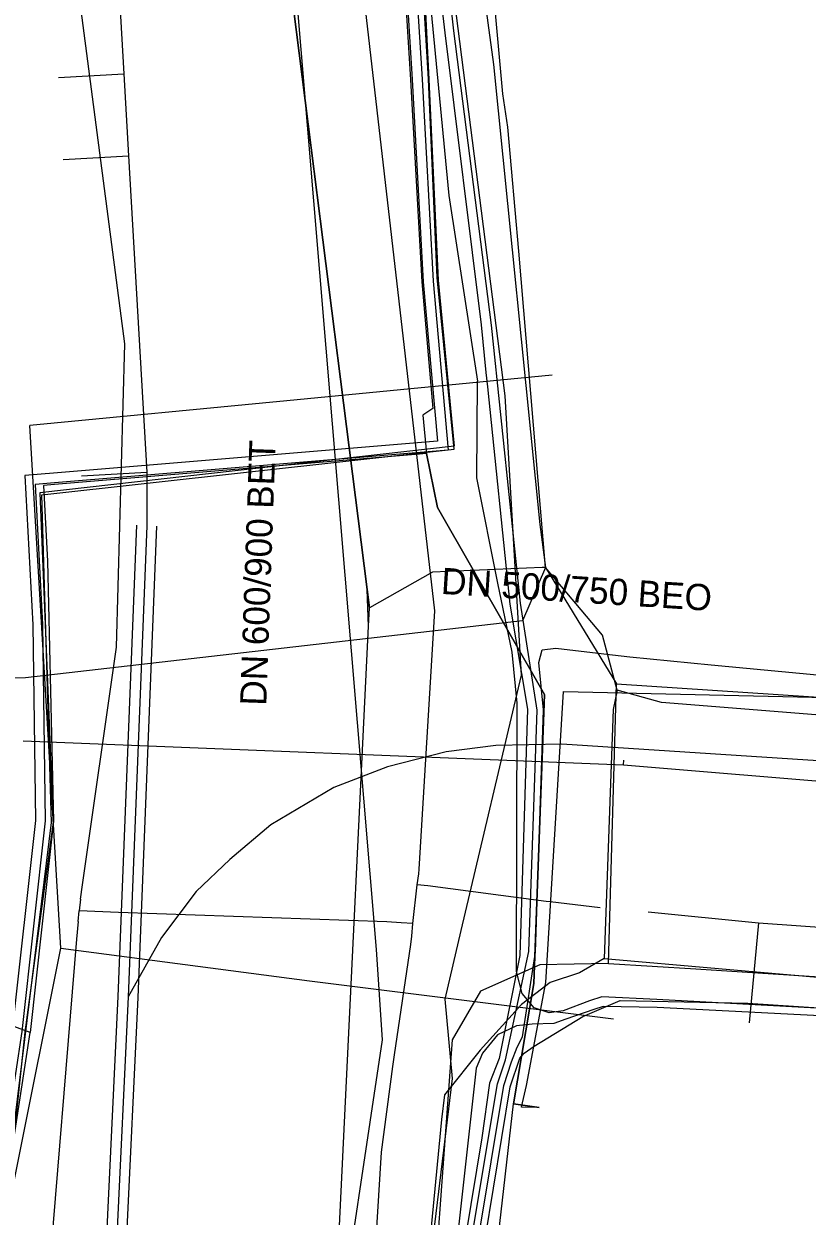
# Model space of a CAD drawing. Extents: x -600309 to -598967, y -1161267 to -1160292.
# Drawn here: x -599086.65 to -599062.77, y -1160939.36 to -1160903.03 of the extents above; entities that cross this region are included whole.
import ezdxf

# ---------------------------------------------------------------- set-up
doc = ezdxf.new("R2010")
doc.units = 0
for name, color, linetype in [('Vrstva 10', 7, 'Continuous'), ('Vrstva 12', 7, 'Continuous'), ('Vrstva 13', 7, 'Continuous'), ('Vrstva 16', 7, 'Continuous'), ('Vrstva 19', 7, 'Continuous'), ('Vrstva 42', 7, 'Continuous'), ('Vrstva 43', 7, 'Continuous'), ('Vrstva 44', 7, 'Continuous'), ('Vrstva 54', 7, 'Continuous'), ('Vrstva 55', 7, 'Continuous'), ('Vrstva 58', 7, 'Continuous'), ('Vrstva 9', 7, 'Continuous')]:
    doc.layers.add(name, color=color, linetype=linetype)

msp = doc.modelspace()

# ---------------------------------------------------------------- linework, layer by layer
at = {"layer": 'Vrstva 10'}
for p, q in [((-599083.771, -1160932.673), (-599083.205, -1160918.311)), ((-599082.605, -1160918.335), (-599083.172, -1160932.697)), ((-599085.318, -1160965.214), (-599083.771, -1160932.67)), ((-599083.172, -1160932.699), (-599084.718, -1160965.242))]:
    msp.add_line(p, q, dxfattribs=at)
for points in [[(-599076.11, -1160920.83), (-599076.18, -1160920.27), (-599081.77, -1160876.19), (-599081.84, -1160875.63)], [(-599078.52, -1160970.46), (-599078.49, -1160969.9), (-599076.14, -1160921.39), (-599076.11, -1160920.83)]]:
    msp.add_lwpolyline(points, dxfattribs=at)
at = {"layer": 'Vrstva 12'}
for points in [[(-599081.84, -1160875.63), (-599076.18, -1160920.27)], [(-599076.75, -1160961.37), (-599073.58, -1160935.17), (-599073.8, -1160932.75), (-599073.32, -1160930.66), (-599071.48, -1160922.88), (-599071.97, -1160914.37), (-599075.73, -1160885.06), (-599076.28, -1160881.3)], [(-599075.51, -1160886.01), (-599075.22, -1160888.16), (-599074.18, -1160890.67), (-599072.33, -1160904.27), (-599070.92, -1160918.29), (-599070.74, -1160919.6)], [(-599070.74, -1160919.6), (-599070.85, -1160919.6), (-599074.19, -1160919.74), (-599076.11, -1160920.83)], [(-599070.74, -1160919.6), (-599068.58, -1160923.14)], [(-599076.18, -1160920.27), (-599076.11, -1160920.83)], [(-599078.52, -1160970.46), (-599078.49, -1160969.9), (-599076.14, -1160921.39), (-599076.11, -1160920.83)], [(-599068.82, -1160931.67), (-599068.58, -1160923.14)], [(-599068.58, -1160923.14), (-599049.94, -1160924.37), (-599041.48, -1160924.88)], [(-599068.82, -1160931.67), (-599070.92, -1160931.71), (-599072.73, -1160932.51), (-599073.59, -1160933.99), (-599074.3, -1160943.74)], [(-599068.82, -1160931.67), (-599066.16, -1160931.83)], [(-599066.16, -1160931.83), (-599060.5, -1160932.19), (-599051.79, -1160932.95), (-599048.6, -1160933.22), (-599040.36, -1160933.93)]]:
    msp.add_lwpolyline(points, dxfattribs=at)
at = {"layer": 'Vrstva 13'}
msp.add_line((-599068.368, -1160925.609), (-599068.355, -1160925.474), dxfattribs=at)
for points in [[(-599086.629, -1161017.283), (-599085.561, -1161009.137), (-599084.815, -1161003.441), (-599084.71, -1161002.64), (-599080.51, -1160970.65), (-599080.1, -1160967.363), (-599079.637, -1160963.654), (-599079.404, -1160961.786), (-599078, -1160950.54), (-599077.19, -1160943.82), (-599075.71, -1160933.99), (-599075.9, -1160931.24), (-599079.535, -1160887.787)], [(-599086.676, -1160924.879), (-599068.368, -1160925.609), (-598967.108, -1160934.03)]]:
    msp.add_lwpolyline(points, dxfattribs=at)
at = {"layer": 'Vrstva 16'}
for points in [[(-599067.61, -1160930.089), (-599064.25, -1160930.43), (-599044.31, -1160931.84), (-599028.16, -1160932.91), (-599026.61, -1160933.02), (-599013.61, -1160934), (-598996.41, -1160935.24), (-598988.49, -1160935.92), (-598977.06, -1160936.9), (-598975.76, -1160937.03), (-598967.108, -1160937.639)], [(-599064.25, -1160930.43), (-599064.53, -1160933.47)]]:
    msp.add_lwpolyline(points, dxfattribs=at)
at = {"layer": 'Vrstva 19'}
for points in [[(-599084.92, -1160929.7), (-599084.859, -1160929.27), (-599083.83, -1160922.03), (-599083.57, -1160912.78), (-599095.07, -1160825.37), (-599102.5, -1160768.3), (-599104.6, -1160752.25), (-599109.62, -1160709.21), (-599119.67, -1160628.93), (-599126.32, -1160575.37), (-599128.11, -1160560.16), (-599133.16, -1160522.31), (-599135.34, -1160510.45), (-599143.35, -1160452.12)], [(-599069.08, -1160929.97), (-599070.6, -1160929.79), (-599070.722, -1160929.774), (-599074.33, -1160929.3), (-599074.66, -1160929.27), (-599074.61, -1160928.93), (-599074.6, -1160928.79), (-599074.12, -1160920.92), (-599077.86, -1160888.45)], [(-599074.85, -1160931.09), (-599074.82, -1160930.83), (-599074.79, -1160930.45), (-599074.66, -1160929.27)], [(-599084.92, -1160929.7), (-599084.96, -1160930.06)], [(-599085, -1160930.39), (-599084.96, -1160930.06)], [(-599075.15, -1160930.43), (-599075.58, -1160930.4), (-599083.77, -1160930.11), (-599084.96, -1160930.06)], [(-599085, -1160930.39), (-599085.044, -1160930.926), (-599085.95, -1160941.91), (-599090.16, -1160981.76)], [(-599074.79, -1160930.45), (-599075.15, -1160930.43)], [(-599085.33, -1161002.59), (-599085.26, -1161001.65), (-599085.24, -1161001.33), (-599085.15, -1161000.04), (-599083.59, -1160988.06), (-599081.79, -1160972.81), (-599080.96, -1160967.67), (-599080.84, -1160966.69), (-599080.29, -1160962.23), (-599080.14, -1160961.28), (-599079.55, -1160955.17), (-599078.82, -1160954.67), (-599077.47, -1160953.6), (-599077.19, -1160953.33), (-599077.12, -1160952.91), (-599076.35, -1160947.15), (-599075.75, -1160937.41), (-599075.4, -1160934.8), (-599075.35, -1160934.45), (-599074.85, -1160931.09)]]:
    msp.add_lwpolyline(points, dxfattribs=at)
at = {"layer": 'Vrstva 42'}
for points in [[(-599074.82, -1160894.78), (-599073.81, -1160903.3), (-599072.71, -1160912.2), (-599072.56, -1160913.652), (-599072.514, -1160914.094), (-599071.83, -1160920.71), (-599071.29, -1160923.91), (-599071.53, -1160931.42), (-599072.16, -1160934.56), (-599072.45, -1160935.31), (-599072.684, -1160936.976), (-599073.187, -1160939.993), (-599073.432, -1160945.786), (-599073.555, -1160946.606), (-599073.561, -1160946.827), (-599073.433, -1160947.128), (-599072.812, -1160947.002)], [(-599072.786, -1160946.793), (-599073.313, -1160946.9), (-599073.36, -1160946.789), (-599073.355, -1160946.624), (-599073.233, -1160945.805), (-599072.988, -1160940.014), (-599072.207, -1160935.333), (-599071.967, -1160934.598), (-599071.25, -1160931.3), (-599071, -1160923.95), (-599071.51, -1160920.68), (-599072.39, -1160912.21), (-599073.54, -1160903.24), (-599074.49, -1160894.73)], [(-599097.718, -1161019.921), (-599095.763, -1161007.197), (-599095.192, -1161003.648), (-599094.56, -1160998.354), (-599094.831, -1160996.489), (-599094.44, -1160992.187), (-599093.567, -1160984.908), (-599091.161, -1160967.703), (-599091.973, -1160964.785), (-599091.582, -1160962.168), (-599090.198, -1160959.942), (-599089.086, -1160950.617), (-599089.687, -1160948.061), (-599089.838, -1160946.015), (-599089.356, -1160943.609), (-599087.792, -1160941.233), (-599087.07, -1160937.623), (-599085.807, -1160927.366), (-599086.108, -1160917.38), (-599073.534, -1160915.996), (-599074.046, -1160910.762), (-599074.316, -1160904.716), (-599074.708, -1160898.099)], [(-599074.921, -1160898.144), (-599074.51, -1160904.711), (-599074.17, -1160910.869), (-599073.712, -1160916.021), (-599085.717, -1160917.019), (-599086.309, -1160917.072), (-599086.08, -1160921.335), (-599086, -1160927.317), (-599086.711, -1160933.739), (-599087.292, -1160937.576), (-599088.039, -1160941.249), (-599089.588, -1160943.548), (-599090.049, -1160946.009), (-599089.921, -1160948.018), (-599089.308, -1160950.68), (-599089.601, -1160953.945), (-599089.737, -1160955.126), (-599090.356, -1160959.945), (-599090.555, -1160960.234), (-599090.822, -1160961.928)], [(-599074.921, -1160898.144), (-599074.51, -1160904.711), (-599074.17, -1160910.869), (-599073.712, -1160916.021), (-599085.717, -1160917.019), (-599086.309, -1160917.072), (-599086.08, -1160921.335), (-599086, -1160927.317), (-599086.711, -1160933.739), (-599087.292, -1160937.576), (-599088.039, -1160941.249), (-599089.588, -1160943.548), (-599090.049, -1160946.009), (-599089.921, -1160948.018), (-599089.308, -1160950.68), (-599089.601, -1160953.945), (-599089.737, -1160955.126), (-599090.356, -1160959.945), (-599090.555, -1160960.234), (-599090.822, -1160961.928)], [(-599075.219, -1160898.176), (-599074.81, -1160904.729), (-599074.47, -1160910.891), (-599074.038, -1160915.747), (-599085.743, -1160916.721), (-599086.625, -1160916.798), (-599086.38, -1160921.345), (-599086.3, -1160927.303), (-599087.009, -1160933.701), (-599087.588, -1160937.524), (-599088.321, -1160941.131), (-599089.872, -1160943.432), (-599090.351, -1160945.991), (-599090.219, -1160948.062), (-599089.612, -1160950.7), (-599089.899, -1160953.915), (-599090.035, -1160955.09), (-599090.644, -1160959.835)], [(-599075.219, -1160898.176), (-599074.81, -1160904.729), (-599074.47, -1160910.891), (-599074.038, -1160915.747), (-599085.743, -1160916.721), (-599086.625, -1160916.798), (-599086.38, -1160921.345), (-599086.3, -1160927.303), (-599087.009, -1160933.701), (-599087.588, -1160937.524), (-599088.321, -1160941.131), (-599089.872, -1160943.432), (-599090.351, -1160945.991), (-599090.219, -1160948.062), (-599089.612, -1160950.7), (-599089.899, -1160953.915), (-599090.035, -1160955.09), (-599090.644, -1160959.835)], [(-599074.921, -1160898.144), (-599074.51, -1160904.711), (-599074.17, -1160910.869), (-599073.712, -1160916.021), (-599085.717, -1160917.019), (-599086.309, -1160917.072), (-599086.08, -1160921.335), (-599086, -1160927.317), (-599086.711, -1160933.739), (-599087.292, -1160937.576), (-599088.039, -1160941.249), (-599089.588, -1160943.548), (-599090.049, -1160946.009), (-599089.921, -1160948.018), (-599089.308, -1160950.68), (-599089.601, -1160953.945), (-599089.737, -1160955.126), (-599090.356, -1160959.945)], [(-599074.921, -1160898.144), (-599074.51, -1160904.711), (-599074.17, -1160910.869), (-599073.712, -1160916.021), (-599085.717, -1160917.019), (-599086.309, -1160917.072), (-599086.08, -1160921.335), (-599086, -1160927.317), (-599086.711, -1160933.739), (-599087.292, -1160937.576), (-599088.039, -1160941.249), (-599089.588, -1160943.548), (-599090.049, -1160946.009), (-599089.921, -1160948.018), (-599089.308, -1160950.68), (-599089.601, -1160953.945), (-599089.737, -1160955.126), (-599090.356, -1160959.945)], [(-599075.219, -1160898.176), (-599074.81, -1160904.729), (-599074.47, -1160910.891), (-599074.038, -1160915.747), (-599085.743, -1160916.721), (-599086.625, -1160916.798), (-599086.38, -1160921.345), (-599086.3, -1160927.303), (-599087.009, -1160933.701), (-599087.588, -1160937.524), (-599088.321, -1160941.131), (-599089.872, -1160943.432), (-599090.351, -1160945.991), (-599090.219, -1160948.062), (-599089.612, -1160950.7), (-599088.763, -1160946.288)], [(-599075.219, -1160898.176), (-599074.81, -1160904.729), (-599074.47, -1160910.891), (-599074.038, -1160915.747), (-599085.743, -1160916.721), (-599086.625, -1160916.798), (-599086.38, -1160921.345), (-599086.3, -1160927.303), (-599087.009, -1160933.701), (-599087.588, -1160937.524), (-599088.321, -1160941.131), (-599089.872, -1160943.432), (-599090.351, -1160945.991), (-599090.219, -1160948.062), (-599089.612, -1160950.7), (-599088.763, -1160946.288)], [(-599072.761, -1160946.584), (-599073.115, -1160946.658), (-599073.154, -1160946.632), (-599073.033, -1160945.825), (-599072.788, -1160940.034), (-599072.013, -1160935.381), (-599071.777, -1160934.66), (-599071.61, -1160934.22), (-599071.45, -1160933.9), (-599071.05, -1160931.322), (-599070.801, -1160923.939), (-599070.95, -1160922.49), (-599070.85, -1160922.11), (-599070.43, -1160922.06), (-599068.965, -1160922.225), (-599068.17, -1160922.32), (-599065.69, -1160922.56), (-599062.46, -1160922.87)], [(-599072.735, -1160946.374), (-599072.88, -1160946.403), (-599072.914, -1160946.381), (-599072.834, -1160945.844), (-599072.589, -1160940.055), (-599071.818, -1160935.429), (-599071.53, -1160934.546), (-599071.4, -1160934.4), (-599071.09, -1160934.18), (-599069.61, -1160933.28), (-599068.47, -1160932.79), (-599064.57, -1160932.87), (-599059.79, -1160933.19)]]:
    msp.add_lwpolyline(points, dxfattribs=at)
at = {"layer": 'Vrstva 43'}
for points in [[(-599070.74, -1160919.6), (-599071.45, -1160921.22), (-599086.6, -1160922.96), (-599089.07, -1160922.98)], [(-599068.56, -1160923.34), (-599069.01, -1160921.66), (-599070.74, -1160919.6)], [(-599059.45, -1160924.33), (-599067.21, -1160923.71), (-599068.56, -1160923.34)]]:
    msp.add_lwpolyline(points, dxfattribs=at)
at = {"layer": 'Vrstva 44'}
for points in [[(-599112.09, -1160608.13), (-599111.98, -1160609.99), (-599109.504, -1160629.736), (-599106.065, -1160655.324), (-599103.642, -1160674.134), (-599100.509, -1160697.439), (-599095.391, -1160735.084), (-599093.34, -1160750.202), (-599089.712, -1160777.364), (-599087.879, -1160792.317), (-599087.434, -1160795.875), (-599084.392, -1160820.684), (-599084.024, -1160822.578), (-599080.74, -1160848.464), (-599078.594, -1160865.22), (-599075.405, -1160890.518), (-599073.694, -1160908.257), (-599072.822, -1160913.918)], [(-599060.79, -1160933.12), (-599067.35, -1160932.76), (-599069.03, -1160932.68), (-599069.4, -1160932.8), (-599070.21, -1160933.11), (-599070.63, -1160933.17), (-599071.09, -1160933.02), (-599071.46, -1160932.58), (-599071.63, -1160931.91), (-599071.61, -1160923.73), (-599071.76, -1160922.18), (-599072.2, -1160920.07), (-599072.84, -1160916.86), (-599072.822, -1160913.918)], [(-599060.78, -1160933.34), (-599067.34, -1160933.01), (-599068.99, -1160932.98), (-599069.27, -1160933.07), (-599070.12, -1160933.36), (-599070.49, -1160933.49), (-599071.15, -1160933.51), (-599071.63, -1160933.57), (-599072.21, -1160933.84), (-599072.67, -1160934.4), (-599072.86, -1160934.86), (-599073.46, -1160940.25), (-599074.2, -1160945.93), (-599074.134, -1160949.259)]]:
    msp.add_lwpolyline(points, dxfattribs=at)
at = {"layer": 'Vrstva 54'}
for points in [[(-599070.54, -1160913.74), (-599078.63, -1160914.52)], [(-599078.63, -1160914.52), (-599086.47, -1160915.27)], [(-599088.228, -1160944.633), (-599085.52, -1160931.2), (-599086.47, -1160915.27)], [(-599085.52, -1160931.2), (-599083.75, -1160931.43)], [(-599083.75, -1160931.43), (-599077.94, -1160932.19), (-599068.671, -1160933.354)]]:
    msp.add_lwpolyline(points, dxfattribs=at)
at = {"layer": 'Vrstva 55'}
for points in [[(-599075.269, -1160898.181), (-599074.86, -1160904.732), (-599074.52, -1160910.894), (-599074.176, -1160914.75), (-599074.482, -1160914.959), (-599074.373, -1160916.126), (-599074.04, -1160917.77)], [(-599070.942, -1160936.057), (-599071.725, -1160935.946), (-599071.097, -1160932.277), (-599070.77, -1160923.47), (-599074.04, -1160917.77), (-599074.373, -1160916.126), (-599074.59, -1160916.144), (-599085.713, -1160917.069), (-599086.057, -1160917.099), (-599085.933, -1160919.403), (-599085.75, -1160927.33), (-599086.464, -1160933.772), (-599089.89, -1160932.51), (-599094.96, -1160929.13), (-599094.856, -1160928.767)], [(-599074.04, -1160917.77), (-599070.77, -1160923.47), (-599071.097, -1160932.277), (-599071.725, -1160935.946), (-599070.942, -1160936.057)], [(-599070.942, -1160936.057), (-599071.476, -1160936.046), (-599071.32, -1160935.38), (-599070.73, -1160932.24), (-599070.2, -1160923.38), (-599049.69, -1160923.84), (-599049.86, -1160925.03), (-599049.78, -1160923.89), (-599047.35, -1160924.14), (-599046.3, -1160924.65), (-599036.7, -1160925.28), (-599024.84, -1160925.97), (-599024.91, -1160926.76)], [(-599090.116, -1160960.037), (-599089.542, -1160955.533), (-599089.056, -1160950.662), (-599089.672, -1160947.982), (-599089.798, -1160946.024), (-599089.352, -1160943.644), (-599088.42, -1160943.46), (-599089.352, -1160943.644), (-599087.804, -1160941.348), (-599087.046, -1160937.62), (-599086.464, -1160933.772), (-599089.89, -1160932.51), (-599094.96, -1160929.13), (-599094.856, -1160928.767)], [(-599102.45, -1161026.64), (-599100.32, -1161026.69), (-599100.4, -1161026.73), (-599100.44, -1161027.32), (-599083.9, -1161028.96), (-599081.18, -1161009.47), (-599079.39, -1160995.93), (-599078.38, -1160987.06), (-599078.02, -1160984), (-599076.79, -1160974.19), (-599075.75, -1160967.73), (-599077.84, -1160967.4), (-599075.75, -1160967.68), (-599073.59, -1160952.31), (-599071.725, -1160935.946), (-599070.942, -1160936.057)]]:
    msp.add_lwpolyline(points, dxfattribs=at)
at = {"layer": 'Vrstva 58'}
for points in [[(-599086.86, -1161033.06), (-599078.59, -1160971.02), (-599078.49, -1160969.9), (-599076.14, -1160921.39), (-599076.18, -1160920.27), (-599081.77, -1160876.19), (-599081.84, -1160875.63), (-599081.91, -1160875.07), (-599089.2, -1160818.766), (-599092.45, -1160793.67), (-599092.6, -1160792.56), (-599099.731, -1160739.009)], [(-599086.86, -1161033.06), (-599078.59, -1160971.02), (-599078.49, -1160969.9), (-599076.14, -1160921.39), (-599076.18, -1160920.27), (-599081.77, -1160876.19), (-599081.84, -1160875.63), (-599081.91, -1160875.07), (-599089.2, -1160818.766), (-599092.45, -1160793.67), (-599092.6, -1160792.56), (-599099.731, -1160739.009)], [(-599086.86, -1161033.06), (-599078.59, -1160971.02), (-599078.49, -1160969.9), (-599076.14, -1160921.39), (-599076.18, -1160920.27), (-599081.77, -1160876.19), (-599081.84, -1160875.63), (-599081.91, -1160875.07), (-599089.2, -1160818.766), (-599092.45, -1160793.67), (-599092.6, -1160792.56), (-599099.731, -1160739.009)], [(-599071.56, -1160909.96), (-599071.89, -1160906.18), (-599072.05, -1160905.16), (-599072.699, -1160898.016)], [(-599074.629, -1160898.16), (-599074.303, -1160904.725), (-599074.017, -1160910.842), (-599073.528, -1160915.898), (-599086.169, -1160917.325), (-599085.761, -1160927.356), (-599086.617, -1160933.758), (-599087.025, -1160937.632), (-599087.882, -1160941.302), (-599089.35, -1160943.626), (-599089.798, -1160945.91)], [(-599070.74, -1160919.6), (-599071.56, -1160909.96)], [(-599070.74, -1160919.6), (-599071.45, -1160921.22), (-599086.6, -1160922.96), (-599089.07, -1160922.98)], [(-599068.56, -1160923.34), (-599069.01, -1160921.66), (-599070.74, -1160919.6)], [(-599068.56, -1160923.34), (-599068.68, -1160923.93), (-599068.96, -1160931.51)], [(-599025.402, -1160926.142), (-599025.56, -1160926.36), (-599028.311, -1160926.435), (-599029.57, -1160926.47), (-599035.292, -1160926.018), (-599040.08, -1160925.64), (-599048.89, -1160924.83), (-599051.29, -1160924.63), (-599051.85, -1160924.37), (-599052.36, -1160924.44), (-599052.99, -1160924.72), (-599058.35, -1160924.43), (-599059.45, -1160924.33), (-599067.21, -1160923.71), (-599068.56, -1160923.34)], [(-599068.96, -1160931.51), (-599069.71, -1160931.95), (-599070.607, -1160932.242), (-599071.48, -1160932.91), (-599072.74, -1160934.31), (-599073.82, -1160935.67), (-599073.92, -1160936.42), (-599074.61, -1160943.6)], [(-599068.96, -1160931.51), (-599061.987, -1160932.124), (-599055.009, -1160932.674), (-599045.84, -1160933.35), (-599040.37, -1160934)]]:
    msp.add_lwpolyline(points, dxfattribs=at)
at = {"layer": 'Vrstva 9'}
for p, q in [((-599085.599, -1160904.668), (-599083.602, -1160904.553)), ((-599085.455, -1160907.164), (-599083.458, -1160907.049)), ((-599084.898, -1160916.808), (-599082.901, -1160916.693)), ((-599084.898, -1160916.808), (-599082.901, -1160916.693)), ((-599082.905, -1160918.323), (-599083.471, -1160932.685)), ((-599083.471, -1160932.685), (-599085.018, -1160965.228))]:
    msp.add_line(p, q, dxfattribs=at)
for points in [[(-599085.39, -1160873.59), (-599085.347, -1160874.333), (-599085.293, -1160875.272), (-599085.229, -1160876.38), (-599085.178, -1160877.268), (-599084.658, -1160886.263), (-599083.602, -1160904.553), (-599083.458, -1160907.049), (-599082.901, -1160916.693), (-599082.905, -1160918.323)], [(-599053.359, -1160926.082), (-599070.247, -1160924.98), (-599072.262, -1160925.025), (-599073.771, -1160925.219), (-599075.56, -1160925.672), (-599077.198, -1160926.298), (-599079.116, -1160927.442), (-599080.366, -1160928.499), (-599081.401, -1160929.47), (-599082.457, -1160930.872), (-599083.471, -1160932.685)]]:
    msp.add_lwpolyline(points, dxfattribs=at)

# ---------------------------------------------------------------- texts
at = {"layer": 'Vrstva 12'}
for s, rotation, p in [('DN 600/900 BET', 87.9603, (-599079.26, -1160923.819)), ('DN 500/750 BEO', 356.3797, (-599073.946, -1160920.4))]:
    msp.add_text(s, height=0.8, rotation=rotation, dxfattribs=at).set_placement(p)

doc.saveas('drawing.dxf')
